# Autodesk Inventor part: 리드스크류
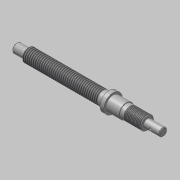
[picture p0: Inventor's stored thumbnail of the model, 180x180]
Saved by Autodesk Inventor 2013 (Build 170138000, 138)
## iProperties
Created: 2020-03
Part Number: 리드스크류
Material: 강철, 연강
Document SubType Name: Modeling
Designer: mduedu
Density: 1 g/cm^3
Author: mduedu
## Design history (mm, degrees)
sketch "스케치1"
  geometry: L1 (0, 0)-(9, 0); L2 (9, 0)-(9, 3.5); L3 (9, 3.5)-(0, 3.5); L4 (0, 3.5)-(0, 0); L5 (9, 0)-(70, 0); L6 (70, 0)-(70, 5); L7 (70, 5)-(9, 5); L8 (9, 5)-(9, 0); L9 (70, 0)-(73, 0); L10 (73, 0)-(73, 7); L11 (73, 7)-(70, 7); L12 (70, 7)-(70, 0); L13 (73, 0)-(83, 0); L14 (83, 0)-(83, 5.5); L15 (83, 5.5)-(73, 5.5); L16 (73, 5.5)-(73, 0); L17 (83, 0)-(99, 0); L18 (99, 0)-(99, 5); L19 (99, 5)-(83, 5); L20 (83, 5)-(83, 0); L21 (99, 0)-(111, 0); L22 (111, 0)-(111, 3); L23 (111, 3)-(99, 3); L24 (99, 3)-(99, 0)
  constraints: 48 end point, 12 parallel, 6 horizontal, 6 perpendicular
  dimensions: "d0" = 61 distance of L6.end L7.end; "d2" = 9 distance of L2.end L3.end; "d3" = 3 distance of L10.end L11.end; "d4" = 10 distance of L14.end L15.end; "d5" = 16 distance of L18.end L19.end; "d6" = 12 distance of L22.end L23.end; "d7" = 7 diameter of L3 L1; "d8" = 10 diameter of L7 L5; "d9" = 14 diameter of L11 L9; "d10" = 11 diameter of L15 L13; "d11" = 10 diameter of L19 L17; "d12" = 6 diameter of L23 L21
revolve "회전1" sketch "스케치1" stored, may be unused: angle "d13" = 90 deg
feature "스레드1" dims "d14" = 57, "d15" = 0
feature "스레드2" dims "d16" = 13, "d17" = 0
chamfer "모따기1" distance "d18" = 0.5; stored, may be unused: second distance "d19" = 2, angle "d20" = 45 deg
sketch "스케치2"
  geometry: L1 (111, 2.5)-(111, -2.5) reference; C1 r 1 at (104, 0); 1 further point
  constraints: 1 centre point, 1 horizontal alignment
  dimensions: "d21" = 2 diameter of C1; "d22" = 7 distance from line of C1.centre L1
extrude "돌출1" cut sketch "스케치2" stored distance "d23" = 10; taper "d24" = 0 deg
node "솔리드1"
